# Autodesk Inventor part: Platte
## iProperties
Created: 2007-01
Material: Standard
Description: Blech lt. Tab.
Document SubType Name: Blech
Designer: R.Pilz
Title: Platte
Author: R.Pilz
ArtNrPrefix: HZ
ArtNrAuto: 0
EDVNum=ArtNr: 0
Bez=Mat: 0
ArtNrBackSpace: 0
EDVNrBackSpace: 0
EDVNrAuto: 0
ProdGruppe: ÜKWW
ProdBezeichnung: Blende
ArtNr: HZG24TE10
EDVNr: L1234
KommaZuschnitt: 0
Zeichnungsnummer: 0G24 TE ST
Konstrukteur: R.Pilz
Erstellungsdatum: 10.01.2007
GesGewicht: 0,6kg
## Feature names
1. Abgeleiteter Körper1 [Tagging]
